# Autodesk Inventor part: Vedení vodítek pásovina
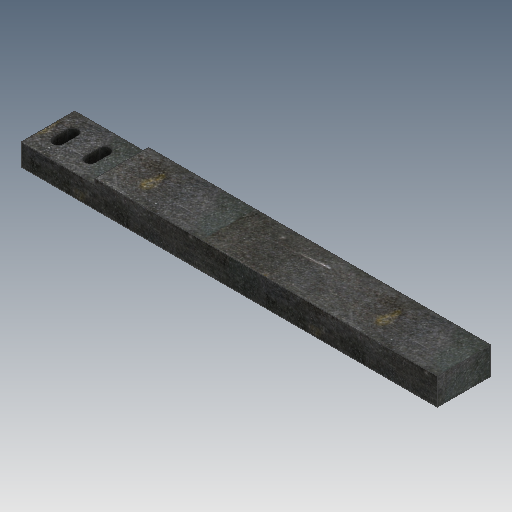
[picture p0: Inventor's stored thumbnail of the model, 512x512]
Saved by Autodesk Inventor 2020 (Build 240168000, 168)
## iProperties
Created: 2025-03
Part Number: Vedení vodítek pásovina
Material: Ocel
Document SubType Name: Modeling
Designer: doma
Density: 7.85 g/cm^3
Appearance: Plech
Mass: 1820.14 g
Surface Area: 398.034 cm^2
Volume: 231.865 cm^3
Author: doma
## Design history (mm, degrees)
sketch "Náčrt1"
  geometry: L1 (0, 0)-(0, 16); L2 (0, 16)-(55, 16); L3 (55, 16)-(55, 20); L4 (0, 0)-(310, 0); L5 (310, 0)-(310, 20); L6 (310, 20)-(55, 20)
  constraints: 12 end point, 4 perpendicular, 1 horizontal, 1 vertical
  dimensions: "d0" = 16 distance of L1.start L1.end; "d1" = 55 distance of L1.end L2.end; "d2" = 4 distance of L2.end L3.end; "d3" = 310 distance of L1.start L4.end
extrude "Vysunutí1" new body sketch "Náčrt1" distance "d4" = 40; taper "d5" = 0 deg
sketch "Náčrt2"
  geometry: L1 (0, 0)-(0, -40) reference; L2 (0, -20)-(13, -20); L3 (13, -20)-(37, -20); L4 (13, -25.5)-(13, -14.5); L5 (17, -25.5)-(17, -14.5); L6 (9, -14.5)-(9, -25.5); L7 (37, -25.5)-(37, -14.5); L8 (41, -25.5)-(41, -14.5); L9 (33, -14.5)-(33, -25.5); A1 r 4 centre (13, -25.5) between (9, -25.5) and (17, -25.5); A2 r 4 centre (13, -14.5) between (17, -14.5) and (9, -14.5); A3 r 4 centre (37, -25.5) between (33, -25.5) and (41, -25.5); A4 r 4 centre (37, -14.5) between (41, -14.5) and (33, -14.5)
  constraints: 20 end point, 8 point on circle, 8 tangent, 4 centre point, 3 midpoint, 2 parallel, 2 perpendicular, 1 horizontal, 1 point on line
  dimensions: "d6" = 13 distance of L2.start L2.end; "d7" = 24 distance of L2.end L3.end; "d8" = 5.5 distance of L2.end L4.end; "d9" = 8 diameter of A2; "d10" = 5.5 distance of L3.end L7.end; "d11" = 8 diameter of A4
extrude "Vysunutí2" cut sketch "Náčrt2" distance "d12" = 40; taper "d13" = 0 deg
sketch "Náčrt3"
  geometry: L1 (13, 25.5)-(13, 14.5); L2 (6, 25.5)-(6, 14.5); L3 (20, 14.5)-(20, 25.5); L4 (37, 14.5)-(37, 25.5); L5 (44, 14.5)-(44, 25.5); L6 (30, 25.5)-(30, 14.5); A1 r 4 centre (13, 25.5) between (17, 25.5) and (9, 25.5) reference; A2 r 4 centre (13, 14.5) between (9, 14.5) and (17, 14.5) reference; A3 r 7 centre (13, 25.5) between (20, 25.5) and (6, 25.5); A4 r 7 centre (13, 14.5) between (6, 14.5) and (20, 14.5); A5 r 4 centre (37, 14.5) between (33, 14.5) and (41, 14.5) reference; A6 r 4 centre (37, 25.5) between (41, 25.5) and (33, 25.5) reference; A7 r 7 centre (37, 14.5) between (30, 14.5) and (44, 14.5); A8 r 7 centre (37, 25.5) between (44, 25.5) and (30, 25.5); 3 further points
  constraints: 16 end point, 8 point on circle, 8 tangent, 4 centre point, 3 parallel, 2 midpoint, 1 vertical
  dimensions: "d14" = 14 diameter of A4; "d15" = 14 diameter of A8
extrude "Vysunutí3" cut sketch "Náčrt3" distance "d16" = 8; taper "d17" = 0 deg
sketch "Náčrt4"
  geometry: L1 (-310, 0)-(-310, 20) reference; L2 (-310, 10)-(-265, 10); 2 further points
  constraints: 2 end point, 1 coincident, 1 horizontal, 1 midpoint
  dimensions: "d18" = 45 distance of L2.start L2.end
hole "Díra1" sketch "Náčrt4" at (-265, 10) diameter "d19" = 4.134; stored, may be unused: countersink angle "d23" = 90 deg, drill point angle "d25" = 118 deg; dims "d20" = 10, "d21" = 4, "d22" = 2, "d24" = 14.2
node "Těleso1"
